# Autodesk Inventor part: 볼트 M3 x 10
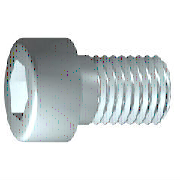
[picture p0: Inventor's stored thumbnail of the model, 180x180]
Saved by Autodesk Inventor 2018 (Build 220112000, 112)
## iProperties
Created: 2012-02
Part Number: 볼트 M3 x 10
Material: 스테인리스강
Description: 6각 소켓 머리 캡 나사
Document SubType Name: Modeling
Standard: ISO 4762
Designer: mduedu
Standard Revision: Fourth edition 2004-03-01
Standards Organization: ISO
Language: ko-KR
Size Designation: M3 x 10
Categories: <MemberInstance><Categories><Category DisplayName="조임쇠" InternalName="e4da775c-781d-43d5-af7c-5136215cf5a6" Mnemonic="FSTN"><Category DisplayName="볼트" InternalN
Density: 8.08 g/cm^3
Mass: 1.0701 g
Surface Area: 2.01851 cm^2
Volume: 0.132438 cm^3
Appearance: 반광택
IsCustomPart: 0
Author: mduedu
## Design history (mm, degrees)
sketch "스케치1"
  geometry: L1 (-0.867, 0)-(10, 0); L2 (10, 0)-(10, 1.5); L3 (10, 1.5)-(1.25, 1.5); L4 (1.25, 1.5)-(0.943, 1.5); L5 (0.943, 1.5)-(0, 1.5); L6 (0, 1.5)-(0, 2.75); L7 (0, 2.75)-(-3, 2.75); L8 (-3, 2.75)-(-3, 1.443); L9 (-3, 1.443)-(-1.7, 1.443); L10 (-1.7, 1.443)-(-0.867, 0); L11 (-5.6, 0)-(12.6, 0) reference; L12 (0, -0.55)-(0, 3.3) reference; L13 (1.25, 1.5)-(0, 1.5)
  constraints: 22 end point, 6 parallel, 2 collinear, 2 perpendicular, 1 horizontal, 1 point on line
  dimensions: "d1" = 8.75 distance from line of L3.end L2 (= GEL); "d2" = 0.30683 distance of L4.end L3.end (computed from GAL); "d3" = 3 distance between parallel lines of L8 L6 (= KOH); "d4" = 1.3 distance of L8.end L9.end (= INTI); "d5" = 60 deg angle of L10 L1; "d6" = 3 diameter of L3 L1 (= GD); "d7" = 3 diameter of L5 L1 (= BDM); "d8" = 2.88675 diameter of L9 L1 (= 1.1547 x SW); "d9" = 5.5 diameter of L7 L1 (= KOD); "d26" = 10 distance between parallel lines of L12 L2 (= NLG)
revolve "본체" sketch "스케치1" stored, may be unused: angle "d10" = 90 deg
sketch "스케치2"
  geometry: L1 (0, -3.85)-(0, 3.85) reference; L2 (-3.85, 0)-(3.85, 0) reference; L3 (1.443, 0)-(0.722, -1.25); L4 (0.722, -1.25)-(-0.722, -1.25); L5 (-0.722, -1.25)-(-1.443, 0); L6 (-1.443, 0)-(-0.722, 1.25); L7 (-0.722, 1.25)-(0.722, 1.25); L8 (0.722, 1.25)-(1.443, 0); 2 further points
  constraints: 12 end point, 1 coincident, 1 horizontal alignment, 1 point on line, 12 other
extrude "슬롯" join sketch "스케치2" stored distance "d11" = 10; taper "d12" = 0 deg
workplane "Work Plane1"
fillet "Fillet2" dims "d30" = 0.1 (= R)
body "Solid1"
fillet "모깎기1" dims "d17" = 0.3 (= RR)
feature "스레드" dims "d13" = 8.75 (= GEL), "d14" = 0
chamfer "모따기1" distance "d15" = 0.30673 (= -0.5 x SPD + 0.5 x GD); stored, may be unused: second distance "d16" = 0.30673 (= GUL), angle "d27" = 45 deg
other parameters: "GD" = 3 [user parameter; used in 2 equation terms], "NLG" = 10 [user parameter; used in 1 equation term], "GEL" = 8.75 [user parameter; used in 2 equation terms], "KOD" = 5.5 [user parameter; used in 1 equation term], "KOH" = 3 [user parameter; used in 1 equation term], "INTI" = 1.3 [user parameter; used in 1 equation term], "GAL" = 0.30673 (= 0.61345 x PTC) [user parameter; used in 1 equation term], "GUL" = 0.30673 (= 0.61345 x PTC) [user parameter; used in 1 equation term], "BDM" = 3 (= NND) [user parameter; used in 1 equation term], "SW" = 2.5 [user parameter; used in 2 equation terms], "RR" = 0.3 [user parameter; used in 1 equation term], "SPD" = 2.38655 (= NND - 1.2269 x PTC) [user parameter; used in 1 equation term], "d19" = 0, "d28" = 0, "d29" = 0, "R" = 0.1 [user parameter; used in 1 equation term], "TOA" = 30 deg [user parameter], "GD1" = 2.38655 (= THREADDIA - 1.2269 x PTC) [user parameter], "THREADDIA" = 3 [user parameter; used in 1 equation term], "FAWI" = 45 deg [user parameter], "PTC" = 0.5 [user parameter; used in 5 equation terms], "NND" = 3 [user parameter; used in 2 equation terms], "E0" = 2.8875 (= 1.155 x SW) [user parameter]
